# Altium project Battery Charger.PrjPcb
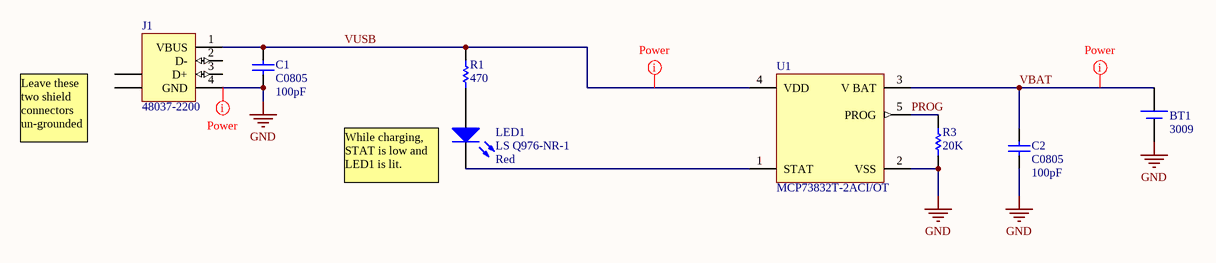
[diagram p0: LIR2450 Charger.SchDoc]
1 sheet, 8 parts. Net scope: global (net labels, ports and power ports of the same name join across sheets).
Board file: LIR2450 Charger.PcbDoc

## Sheet LIR2450 Charger.SchDoc: CR2450 Charger
size Letter; DrawnBy: Jay Kickliter; Revision: 1; SheetNumber: 1; SheetTotal: 1; WebAddress: www.chasingtrons.com; PageSetup: Record=PageOptions|CenterHorizontal=True|CenterVertical=True|PrintScale=0.98|XCorrection=1.00|YCorrection=1.00|PrintKind=0|BorderSize=5000000|LeftOffset=0|BottomOffset=0|Orientation=2|PaperLength=1000|PaperWidth=1000|Scale=100|PaperSource=15|PrintQuality=600|MediaType=1|DitherType=10|PaperKind=Letter|PrintScaleMode=1

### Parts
BT1  3009  [3009]
C1  C0805  value 100pF  [0805]
C2  C0805  value 100pF  [0805]
J1  48037-2200  [480372200]
LED1  LS Q976-NR-1  Color: Red  [LED-SMD-0603-RED]
R1  470  [RESC2012N]
R3  20K  [RESC2012N]
U1  MCP73832T-2ACI/OT  [SOT-23-OT5_M]

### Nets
GND: BT1.2(-) C1.2 C2.1 J1.4(GND) R3.1 U1.2(VSS)
PROG: R3.2 U1.5(PROG)
VBAT: BT1.1(+) C2.2 U1.3(V_BAT)
VUSB: C1.1 J1.1(VBUS) R1.2 U1.4(VDD)
NetLED1_1: LED1.1(A) R1.1
NetLED1_2: LED1.2(K) U1.1(STAT)

Not connected (* = marked no-connect by the designer): J1 2(D-) 3(D+) 5(SHLD) 6(SHLD)

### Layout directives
net class Undefined: GND, VBAT, VUSB

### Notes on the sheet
- Leave these two shield connectors un-grounded
- (near LED1) While charging, STAT is low and LED1 is lit.
  When charge complete, STAT goes high and lights LED2

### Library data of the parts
BT1 = 3009: Battery Holder, CR2450, Keystone model 3009; Manufacturer: Keystone Electronics; Description: HOLDER BATTERY COIN 24MM DIA THM; Battery Type, Function: Coin Cell, Retainer; Style: Retainer; Battery Cell Size: Coin, 24.0mm; Number of Cells: 1; Battery Series: 2450
C1 C2 = C0805: Ceramic Chip Capacitor - Standard; Note: Footprint corresponds to dimensions for bulk cassette packaging. This case size has tightened tolerances.
J1 = 48037-2200: USB 1.1, Right Angle, SMT, A Type, Receptacle, 4 Position, White; ContactMaterial: Nickle; ContactPlating: Gold; PCB_Layout: Complies with manufacturer's recommendation.; DrillSize: Corresponds to nominal value.; PanelGround: Without
LED1 = LS Q976-NR-1: LED CHIPLED 633NM RED 0603 SMD; Manufacturer: OSRAM Opto Semiconductors Inc; Luminous Flux @ Current - Test: 330 mlm; Millicandela Rating: 104mcd; Current - Test: 20mA; Wavelength - Peak: 645nm; Voltage - Forward (Vf) Typ: 2V; Lens Type: Diffused; Lens Style/Size: Rectangle with Flat Top, 1mm x 0.8mm; Viewing Angle: 160°
R1 = ERJ-6GEYJ471V: RES 470 OHM 1/8W 5% 0805 SMD; Manufacturer: Panasonic - ECG; Power (Watts): 0.125W, 1/8W; Temperature Coefficient: ±200ppm/°C
R3 = ERJ-6GEYJ203V: RES 20K OHM 1/8W 5% 0805 SMD; Manufacturer: Panasonic - ECG; Power (Watts): 0.125W, 1/8W; Temperature Coefficient: ±200ppm/°C
U1 = MCP73832T-2ACI/OT: IC LI-ION/LI-POLY CTRLR SOT23-5; Manufacturer: Microchip Technology; Function: Charge Management; Battery Chemistry: Lithium-Ion (Li-Ion), Lithium-Polymer (Li-Pol); Voltage - Supply: 3.75 V ~ 6 V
